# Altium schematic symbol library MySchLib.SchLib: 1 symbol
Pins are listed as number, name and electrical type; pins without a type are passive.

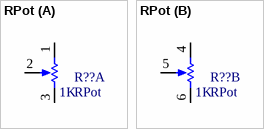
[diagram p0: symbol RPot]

## RPot
designator R??  value 1K
Potentiometer; Sim Note: Enter the Resistance value and the set point into parameter fields.; Set Position: 0.5
footprint VR5 (Thru-Hole; 3 Leads)
simulation model POT (Potentiometer)
footprint RP
part A pins: 1 TOP, 2 TAP, 3 BOT
part B pins: 4 TOP, 5 TAP, 6 BOT
1 alternate drawing of the same symbol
